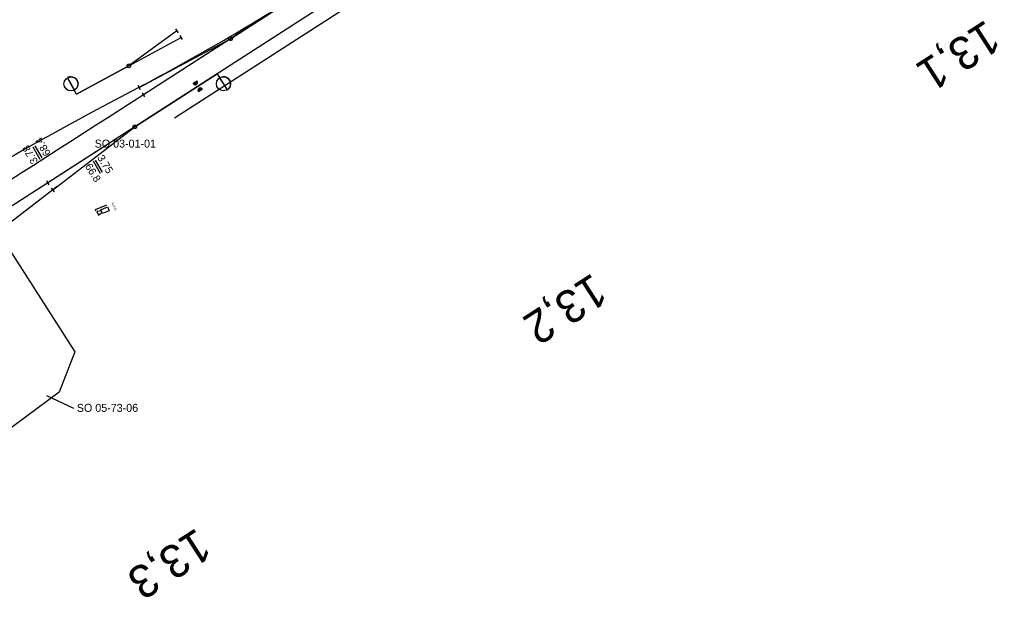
# Model space of a CAD drawing. Extents: x -723225 to -722352, y -1040354 to -1039760.
# Drawn here: x -722559.9 to -722352.2, y -1040092 to -1039969.1 of the extents above; entities that cross this region are included whole.
import ezdxf

# ---------------------------------------------------------------- set-up
doc = ezdxf.new("R2010")
doc.units = 0
for name, color, linetype in [('_PS_SO_číslo', 7, 'Continuous'), ('PS 05_01_01', 7, 'Continuous'), ('PS 05_02_22', 7, 'Continuous'), ('SO 03_01_01', 7, 'Continuous'), ('SO 05_73_06', 7, 'Continuous')]:
    doc.layers.add(name, color=color, linetype=linetype)

msp = doc.modelspace()

# ---------------------------------------------------------------- linework, layer by layer
at = {"layer": '_PS_SO_číslo'}
msp.add_line((-722554.15, -1040049.05), (-722548.42, -1040051.72), dxfattribs=at)
at = {"layer": 'PS 05_02_22'}
for p, q in [((-722541.38, -1040008.56), (-722543.81, -1040009.6)), ((-722542.63, -1040009.57), (-722541.21, -1040008.97)), ((-722541.21, -1040008.97), (-722540.86, -1040009.78)), ((-722543.81, -1040009.6), (-722543.73, -1040009.8)), ((-722542.54, -1040009.78), (-722543.44, -1040009.92)), ((-722543.44, -1040009.92), (-722543.09, -1040010.73)), ((-722543.09, -1040010.73), (-722542.37, -1040010.18)), ((-722542.28, -1040010.38), (-722542.63, -1040009.57)), ((-722540.86, -1040009.78), (-722542.28, -1040010.38))]:
    msp.add_line(p, q, dxfattribs=at)
at = {"layer": 'SO 03_01_01'}
for p, q in [((-722400.19, -1039899.16), (-722541.14, -1039990)), ((-722397.63, -1039903.16), (-722561.45, -1040008.75)), ((-722479.22, -1039959.32), (-722526.95, -1039990.08)), ((-722526.77, -1039971.15), (-722526.18, -1039971.95)), ((-722525.82, -1039972.52), (-722525.34, -1039973.4)), ((-722533.44, -1039982.99), (-722543.38, -1039988.28)), ((-722534.73, -1039983.11), (-722534.26, -1039983.99)), ((-722522.88, -1039982.88), (-722522.36, -1039982.37)), ((-722522.69, -1039982.98), (-722522.07, -1039982.36)), ((-722522.4, -1039982.97), (-722522.08, -1039982.65)), ((-722522.14, -1039982.22), (-722522.14, -1039982.22)), ((-722521.97, -1039984.24), (-722521.41, -1039983.67)), ((-722521.89, -1039984.44), (-722521.2, -1039983.75)), ((-722521.1, -1039983.93), (-722521.06, -1039983.89)), ((-722521.05, -1039983.9), (-722521.05, -1039983.9)), ((-722533.84, -1039984.71), (-722533.3, -1039985.55)), ((-722551.89, -1040004.64), (-722564.35, -1040014.22)), ((-722554.16, -1040003.45), (-722553.62, -1040004.29)), ((-722553.14, -1040004.97), (-722552.53, -1040005.76))]:
    msp.add_line(p, q, dxfattribs=at)
for points in [[(-722534.5, -1039983.55), (-722515.08, -1039973.21), (-722497.6, -1039961.94), (-722515.08, -1039973.21), (-722533.57, -1039985.13)], [(-722526.47, -1039971.55), (-722536.66, -1039978.99), (-722547.74, -1039985.01), (-722536.66, -1039978.99), (-722525.58, -1039972.96)], [(-722552.84, -1040005.37), (-722535.4, -1039991.96), (-722517.92, -1039980.69), (-722535.4, -1039991.96), (-722553.89, -1040003.87)], [(-722549.65, -1039981.5), (-722548.21, -1039984.13)], [(-722547.74, -1039985.01), (-722549.65, -1039981.5)], [(-722517.92, -1039980.69), (-722515.75, -1039984.05)], [(-722517.38, -1039981.53), (-722515.75, -1039984.05)], [(-722522.98, -1039982.76), (-722522.98, -1039982.76), (-722522.14, -1039982.22), (-722522.14, -1039982.22)], [(-722522.14, -1039982.22), (-722522.98, -1039982.76), (-722522.98, -1039982.76)], [(-722522.14, -1039982.22), (-722522.14, -1039982.22), (-722522.14, -1039982.22)], [(-722521.9, -1039984.44), (-722521.9, -1039984.44), (-722521.05, -1039983.9), (-722521.05, -1039983.9)], [(-722521.9, -1039984.44), (-722521.9, -1039984.44), (-722521.05, -1039983.9)], [(-722521.05, -1039983.9), (-722521.05, -1039983.9), (-722521.05, -1039983.9)], [(-722541.14, -1039990), (-722543.76, -1039991.69), (-722546.38, -1039993.38), (-722549, -1039995.07), (-722551.63, -1039996.76), (-722554.25, -1039998.45), (-722556.87, -1040000.14), (-722559.5, -1040001.82), (-722562.12, -1040003.51)], [(-722557.06, -1039996.22), (-722555.56, -1039998.81)], [(-722556.63, -1039995.97), (-722555.13, -1039998.56)], [(-722542.67, -1040001.86), (-722544.16, -1039999.25)], [(-722542.23, -1040001.61), (-722543.72, -1039999.01)]]:
    msp.add_lwpolyline(points, dxfattribs=at)
for centre, radius in [((-722515.08, -1039973.21), 0.4), ((-722536.66, -1039978.99), 0.4), ((-722548.93, -1039982.81), 1.5), ((-722516.56, -1039982.79), 1.5), ((-722535.4, -1039991.96), 0.4)]:
    msp.add_circle(centre, radius, dxfattribs=at)
for centre, radius, start, end in [((-722768.48, -1039541.67), 500, 298.039, 302.8026), ((-722548.93, -1039982.81), 1.5, 0, 118.5354), ((-722516.56, -1039982.79), 1.5, 0, 122.8026), ((-722548.93, -1039982.81), 1.5, 298.5354, 360), ((-722522.56, -1039982.49), 0.5, 212.5047, 33.1017), ((-722522.56, -1039982.49), 0.5, 212.5047, 33.1005), ((-722522.56, -1039982.49), 0.5, 33.1005, 33.1017), ((-722521.48, -1039984.17), 0.5, 32.5035, 213.1005), ((-722521.48, -1039984.17), 0.5, 32.5046, 213.1005), ((-722521.48, -1039984.17), 0.5, 32.5035, 32.5046), ((-722516.56, -1039982.79), 1.5, 302.8026, 360), ((-722214.33, -1040606.12), 700, 118.03896, 120.93566)]:
    msp.add_arc(centre, radius, start, end, dxfattribs=at)
at = {"layer": 'SO 05_73_06'}
msp.add_lwpolyline([(-722581.73, -1039987.28), (-722548.11, -1040039.79), (-722551.46, -1040048.32), (-722565.54, -1040058.78)], dxfattribs=at)

# ---------------------------------------------------------------- texts
at = {"layer": '_PS_SO_číslo'}
for s, p in [('SO 03-01-01', (-722543.91, -1039996.36)), ('SO 05-73-06', (-722547.7, -1040052.52))]:
    msp.add_text(s, height=1.7, dxfattribs=at).set_placement(p)
at = {"layer": 'PS 05_01_01'}
msp.add_text('ROV1', height=0.5, rotation=293.9343, dxfattribs=at).set_placement((-722540.36, -1040008.17))
at = {"layer": 'SO 03_01_01'}
for s, height, rotation, p in [('13,1', 7, 212.8026, (-722354.65, -1039969.03)), ('68.4', 1.6, 119.7842, (-722553.19, -1039997.6)), ('3.78', 1.6, 119.7842, (-722555.9, -1039999.27)), ('3.75', 1.6, 301.8677, (-722543.44, -1039998.52)), ('66.8', 1.6, 301.8677, (-722546.04, -1040000.34)), ('13,2', 7, 212.8026, (-722438.17, -1040022.86)), ('13,3', 7, 212.7759, (-722522.22, -1040077.03))]:
    msp.add_text(s, height=height, rotation=rotation, dxfattribs=at).set_placement(p)

doc.saveas('drawing.dxf')
